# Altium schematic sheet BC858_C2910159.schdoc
size 127 x 101 mm
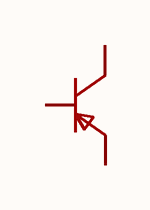
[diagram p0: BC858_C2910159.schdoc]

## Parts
Q?  bc858(range:220-475)  [SOT-23-3_L2.9-W1.3-P1.90-LS2.4-BR]  (value not drawn)

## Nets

Not connected (* = marked no-connect by the designer): Q? 1(B) 2(E) 3(C)

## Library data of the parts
Q? = bc858(range:220-475): 晶体管类型:PNP;集电极电流(Ic):100mA;集射极击穿电压(Vceo):30V;耗散功率(Pd):200mW;直流电流增益(hFE):220;; Manufacturer: CJ(江苏长电/长晶); Symbol: BC858_C2910159; AddInBom: yes; ModelId: c62791f0466c4ae2a892c056b845b0ca; ModelName: SOT-23-3P_L2.9-W1.3-H1.0-LS2.4-P0.95; ModelTransform: 98.425,114.173,0,180,0,0,0.0005,-0.0005,0; type: PNP; Current - Collector(Ic): 100mA; Collector - Emitter Voltage VCEO: 30V; Pd - Power Dissipation: 200mW; DC Current Gain: 220; Transition frequency(fT): 100MHz; Current - Collector Cutoff: 100nA; Vce Saturation(VCE(sat)): 500mV; Number: 1个PNP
